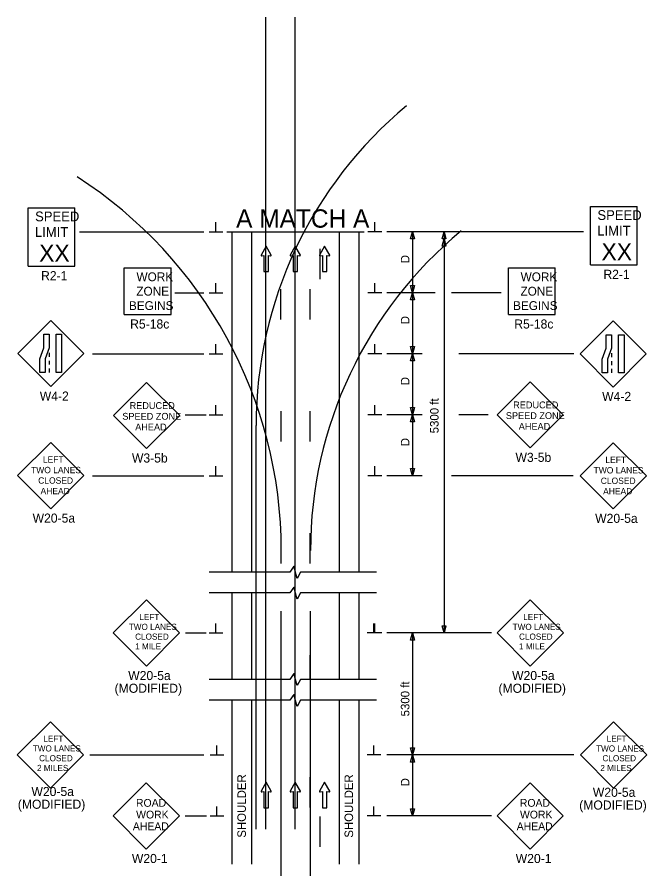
# Model space of a CAD drawing. Extents: x 16728 to 19508, y 5553 to 7079.
# Drawn here: x 17851 to 18367, y 6375 to 7079 of the extents above; entities that cross this region are included whole.
import ezdxf

# ---------------------------------------------------------------- set-up
doc = ezdxf.new("R2010")
doc.units = 0
for name, color, linetype in [('ALI_LEGAL_EX', 7, 'Continuous'), ('MT_SCRATCH_LEVEL_E', 7, 'Continuous'), ('PAVT_EDGE_EX', 7, 'Continuous'), ('TRAFFIC_SIGNS_PR', 7, 'Continuous'), ('TYPICAL_TEXT_DIMEN_PR', 7, 'Continuous')]:
    doc.layers.add(name, color=color, linetype=linetype)

msp = doc.modelspace()

# ---------------------------------------------------------------- linework, layer by layer
at = {"layer": 'ALI_LEGAL_EX'}
for p, q in [((18054.48, 7078.99), (18054.48, 6413.36)), ((18078.48, 7078.99), (18078.48, 6413.36)), ((18054.48, 6981.91), (18054.48, 6413.36)), ((18078.48, 6981.91), (18078.48, 6413.36)), ((18046.81, 6413.36), (18046.81, 6744.25)), ((18067.05, 6592.15), (18067.05, 6515)), ((18067.45, 6375.08), (18067.45, 6591.74)), ((18091.05, 6592.15), (18091.05, 6515)), ((18091.45, 6375.08), (18091.45, 6591.74)), ((18067.05, 6569), (18067.05, 6375.08)), ((18091.05, 6569), (18091.05, 6375.08))]:
    msp.add_line(p, q, dxfattribs=at)
for points in [[(18099.19, 6889.18), (18099.19, 6864.18)], [(18067.05, 6831.03), (18067.05, 6856.03)], [(18091.05, 6831.03), (18091.05, 6856.03)], [(18067.05, 6756.03), (18067.05, 6731.03)], [(18067.05, 6756.03), (18067.05, 6731.03)], [(18091.05, 6731.03), (18091.05, 6756.03)], [(18067.05, 6656.03), (18067.05, 6631.03)], [(18067.05, 6656.03), (18067.05, 6631.03)], [(18091.05, 6631.03), (18091.05, 6656.03)], [(18067.05, 6556.03), (18067.05, 6531.03)], [(18067.05, 6556.03), (18067.05, 6536.14)], [(18091.05, 6536.14), (18091.05, 6556.03)], [(18067.05, 6456.03), (18067.05, 6431.03)], [(18067.05, 6456.03), (18067.05, 6431.03)], [(18091.05, 6431.03), (18091.05, 6456.03)], [(18099.19, 6423.79), (18099.19, 6398.79)]]:
    msp.add_lwpolyline(points, dxfattribs=at)
for centre, radius, start, end in [((18386.81, 6744.25), 340, 129.56655, 180), ((17703.45, 6641.72), 364, 0, 57.29578), ((18431.45, 6641.72), 340, 129.56655, 180)]:
    msp.add_arc(centre, radius, start, end, dxfattribs=at)
at = {"layer": 'MT_SCRATCH_LEVEL_E'}
for p, q in [((18055.05, 6891.26), (18050.94, 6884.02)), ((18059.19, 6884.02), (18055.05, 6891.26)), ((18078.95, 6891.26), (18074.84, 6884.02)), ((18083.1, 6884.02), (18078.95, 6891.26)), ((18103, 6891.26), (18098.89, 6884.02)), ((18107.15, 6884.02), (18103, 6891.26)), ((18051.42, 6883.34), (18053.19, 6883.65)), ((18053.19, 6883.65), (18053.19, 6870.4)), ((18056.94, 6870.4), (18056.94, 6883.65)), ((18056.94, 6883.65), (18058.71, 6883.34)), ((18075.32, 6883.34), (18077.1, 6883.65)), ((18077.1, 6883.65), (18077.1, 6870.4)), ((18080.84, 6870.4), (18080.84, 6883.65)), ((18080.84, 6883.65), (18082.62, 6883.34)), ((18099.37, 6883.34), (18101.15, 6883.65)), ((18101.15, 6883.65), (18101.15, 6870.4)), ((18104.89, 6870.4), (18104.89, 6883.65)), ((18104.89, 6883.65), (18106.67, 6883.34)), ((18053.19, 6870.4), (18056.94, 6870.4)), ((18077.1, 6870.4), (18080.84, 6870.4)), ((18101.15, 6870.4), (18104.89, 6870.4)), ((18055.05, 6451.78), (18050.94, 6444.54)), ((18059.19, 6444.54), (18055.05, 6451.78)), ((18078.95, 6451.78), (18074.84, 6444.54)), ((18083.1, 6444.54), (18078.95, 6451.78)), ((18103, 6451.78), (18098.89, 6444.54)), ((18107.15, 6444.54), (18103, 6451.78)), ((18051.42, 6443.86), (18053.19, 6444.17)), ((18053.19, 6444.17), (18053.19, 6430.92)), ((18056.94, 6430.92), (18056.94, 6444.17)), ((18056.94, 6444.17), (18058.71, 6443.86)), ((18075.32, 6443.86), (18077.1, 6444.17)), ((18077.1, 6444.17), (18077.1, 6430.92)), ((18080.84, 6430.92), (18080.84, 6444.17)), ((18080.84, 6444.17), (18082.62, 6443.86)), ((18099.37, 6443.86), (18101.15, 6444.17)), ((18101.15, 6444.17), (18101.15, 6430.92)), ((18104.89, 6430.92), (18104.89, 6444.17)), ((18104.89, 6444.17), (18106.67, 6443.86)), ((18053.19, 6430.92), (18056.94, 6430.92)), ((18077.1, 6430.92), (18080.84, 6430.92)), ((18101.15, 6430.92), (18104.89, 6430.92))]:
    msp.add_line(p, q, dxfattribs=at)
for centre, start, end in [((18051.34, 6883.8), 150.42484, 279.96381), ((18058.78, 6883.8), 260.03619, 29.77312), ((18075.25, 6883.8), 150.42484, 279.96381), ((18082.69, 6883.8), 260.03619, 29.77312), ((18099.3, 6883.8), 150.42484, 279.96381), ((18106.74, 6883.8), 260.03619, 29.77312), ((18051.34, 6444.32), 150.42484, 279.96381), ((18058.78, 6444.32), 260.03619, 29.77312), ((18075.25, 6444.32), 150.42484, 279.96381), ((18082.69, 6444.32), 260.03619, 29.77312), ((18099.3, 6444.32), 150.42484, 279.96381), ((18106.74, 6444.32), 260.03619, 29.77312)]:
    msp.add_arc(centre, 0.463, start, end, dxfattribs=at)
at = {"layer": 'PAVT_EDGE_EX'}
for p, q in [((18027.05, 6903.04), (18027.05, 6624.09)), ((18043.05, 6903.04), (18043.05, 6624.09)), ((18115.05, 6903.04), (18115.05, 6624.09)), ((18131.05, 6903.04), (18131.05, 6624.09)), ((18027.05, 6606.96), (18027.05, 6536.14)), ((18043.05, 6606.96), (18043.05, 6536.14)), ((18115.05, 6606.96), (18115.05, 6536.14)), ((18131.05, 6606.96), (18131.05, 6536.14)), ((18027.05, 6519), (18027.05, 6384.62)), ((18043.05, 6519), (18043.05, 6384.62)), ((18115.05, 6519), (18115.05, 6384.62)), ((18131.05, 6519), (18131.05, 6384.62))]:
    msp.add_line(p, q, dxfattribs=at)
at = {"layer": 'TRAFFIC_SIGNS_PR'}
for p, q in [((17859.91, 6922.8), (17898.31, 6922.8)), ((17859.91, 6874.8), (17859.91, 6922.8)), ((17898.31, 6874.8), (17898.31, 6922.8)), ((18320.85, 6923.9), (18359.25, 6923.9)), ((18320.85, 6875.9), (18320.85, 6923.9)), ((18359.25, 6875.9), (18359.25, 6923.9)), ((17859.91, 6874.8), (17898.31, 6874.8)), ((17938.79, 6835.18), (17938.79, 6873.58)), ((17938.79, 6873.58), (17977.19, 6873.58)), ((17977.19, 6835.18), (17977.19, 6873.58)), ((18253.66, 6835.18), (18253.66, 6873.58)), ((18253.66, 6873.58), (18292.06, 6873.58)), ((18292.06, 6835.18), (18292.06, 6873.58)), ((18320.85, 6875.9), (18359.25, 6875.9)), ((17938.79, 6835.18), (17977.19, 6835.18)), ((18253.66, 6835.18), (18292.06, 6835.18)), ((17878.55, 6830.41), (17851.4, 6803.26)), ((17905.71, 6803.26), (17878.55, 6830.41)), ((18339.51, 6830.11), (18312.36, 6802.96)), ((18366.67, 6802.96), (18339.51, 6830.11)), ((17851.4, 6803.26), (17878.55, 6776.11)), ((17877.31, 6803.75), (17877.31, 6800.55)), ((17878.55, 6776.11), (17905.71, 6803.26)), ((18312.36, 6802.96), (18339.51, 6775.81)), ((18338.27, 6803.45), (18338.27, 6800.25)), ((18339.51, 6775.81), (18366.67, 6802.96)), ((17877.31, 6797.35), (17877.31, 6794.15)), ((18338.27, 6797.05), (18338.27, 6793.85)), ((17877.31, 6790.95), (17877.31, 6787.75)), ((18338.27, 6790.65), (18338.27, 6787.45)), ((17957.12, 6779.63), (17929.96, 6752.48)), ((17984.27, 6752.48), (17957.12, 6779.63)), ((18271.51, 6780.17), (18244.36, 6753.02)), ((18298.66, 6753.02), (18271.51, 6780.17)), ((17929.96, 6752.48), (17957.12, 6725.33)), ((17957.12, 6725.33), (17984.27, 6752.48)), ((18244.36, 6753.02), (18271.51, 6725.87)), ((18271.51, 6725.87), (18298.66, 6753.02)), ((17878.5, 6730.36), (17851.35, 6703.21)), ((17905.66, 6703.21), (17878.5, 6730.36)), ((18339.61, 6730.16), (18312.46, 6703)), ((18366.76, 6703), (18339.61, 6730.16)), ((17851.35, 6703.21), (17878.5, 6676.06)), ((17878.5, 6676.06), (17905.66, 6703.21)), ((18312.46, 6703), (18339.61, 6675.85)), ((18339.61, 6675.85), (18366.76, 6703)), ((17956.88, 6601.39), (17929.69, 6574.2)), ((17984.06, 6574.2), (17956.88, 6601.39)), ((18271.53, 6601.39), (18244.35, 6574.2)), ((18298.72, 6574.2), (18271.53, 6601.39)), ((17929.69, 6574.2), (17956.88, 6547.01)), ((17956.88, 6547.01), (17984.06, 6574.2)), ((18244.35, 6574.2), (18271.53, 6547.02)), ((18271.53, 6547.02), (18298.72, 6574.2)), ((17878.18, 6501.43), (17850.99, 6474.24)), ((17905.36, 6474.24), (17878.18, 6501.43)), ((18339.92, 6501.39), (18312.73, 6474.2)), ((18367.11, 6474.2), (18339.92, 6501.39)), ((17850.99, 6474.24), (17878.18, 6447.06)), ((17878.18, 6447.06), (17905.36, 6474.24)), ((18312.73, 6474.2), (18339.92, 6447.01)), ((18339.92, 6447.01), (18367.11, 6474.2)), ((17956.85, 6451.32), (17929.69, 6424.16)), ((17984, 6424.16), (17956.85, 6451.32)), ((18271.49, 6451.32), (18244.34, 6424.16)), ((18298.64, 6424.16), (18271.49, 6451.32)), ((17929.69, 6424.16), (17956.85, 6397.01)), ((17956.85, 6397.01), (17984, 6424.16)), ((18244.34, 6424.16), (18271.49, 6397.01)), ((18271.49, 6397.01), (18298.64, 6424.16))]:
    msp.add_line(p, q, dxfattribs=at)
for points in [[(17877.31, 6819), (17877.31, 6807.82), (17873.96, 6798.93), (17873.96, 6787.75), (17869.47, 6787.75), (17869.47, 6798.93), (17872.81, 6807.82), (17872.81, 6819)], [(17887.44, 6819), (17887.44, 6787.75), (17882.95, 6787.75), (17882.95, 6819)], [(18338.27, 6818.7), (18338.27, 6807.52), (18334.92, 6798.63), (18334.92, 6787.45), (18330.43, 6787.45), (18330.43, 6798.63), (18333.77, 6807.52), (18333.77, 6818.7)], [(18348.4, 6818.7), (18348.4, 6787.45), (18343.91, 6787.45), (18343.91, 6818.7)]]:
    msp.add_lwpolyline(points, close=True, dxfattribs=at)
at = {"layer": 'TYPICAL_TEXT_DIMEN_PR'}
for p, q in [((18013.92, 6903.04), (18013.92, 6910.83)), ((18144.17, 6903.04), (18144.17, 6910.83)), ((17902.17, 6903.04), (18004.05, 6903.04)), ((18008.3, 6903.04), (18019.55, 6903.04)), ((18022.72, 6903.04), (18135.37, 6903.04)), ((18149.8, 6903.04), (18138.55, 6903.04)), ((18315.22, 6903.04), (18154.05, 6903.04)), ((18173.48, 6897.18), (18175.05, 6903.04)), ((18175.05, 6903.04), (18175.05, 6853.04)), ((18175.05, 6903.04), (18176.62, 6897.18)), ((18199.32, 6897.18), (18200.89, 6903.04)), ((18200.89, 6903.04), (18200.89, 6574.2)), ((18200.89, 6903.04), (18202.46, 6897.18)), ((18175.05, 6897.18), (18173.48, 6897.18)), ((18176.62, 6897.18), (18175.05, 6897.18)), ((18199.32, 6891.4), (18200.89, 6897.27)), ((18200.89, 6897.18), (18199.32, 6897.18)), ((18200.89, 6891.4), (18199.32, 6891.4)), ((18200.89, 6897.27), (18202.46, 6891.4)), ((18202.46, 6897.18), (18200.89, 6897.18)), ((18202.46, 6891.4), (18200.89, 6891.4)), ((18013.92, 6853.04), (18013.92, 6860.83)), ((18144.17, 6853.04), (18144.17, 6860.83)), ((18175.05, 6853.04), (18173.48, 6858.91)), ((18173.48, 6858.91), (18175.05, 6858.91)), ((18175.05, 6858.91), (18176.62, 6858.91)), ((18176.62, 6858.91), (18175.05, 6853.04)), ((17980.24, 6853.04), (18004.05, 6853.04)), ((18008.3, 6853.04), (18019.55, 6853.04)), ((18149.8, 6853.04), (18138.55, 6853.04)), ((18193.6, 6853.04), (18154.05, 6853.04)), ((18173.48, 6847.18), (18175.05, 6853.04)), ((18175.05, 6853.04), (18175.05, 6803.04)), ((18175.05, 6853.04), (18176.62, 6847.18)), ((18247.8, 6853.04), (18206.89, 6853.04)), ((18175.05, 6847.18), (18173.48, 6847.18)), ((18176.62, 6847.18), (18175.05, 6847.18)), ((18013.92, 6803.04), (18013.92, 6810.83)), ((18144.17, 6803.04), (18144.17, 6810.83)), ((18175.05, 6803.04), (18173.48, 6808.91)), ((18173.48, 6808.91), (18175.05, 6808.91)), ((18175.05, 6808.91), (18176.62, 6808.91)), ((18176.62, 6808.91), (18175.05, 6803.04)), ((17912.81, 6803.04), (18004.05, 6803.04)), ((18008.3, 6803.04), (18019.55, 6803.04)), ((18149.8, 6803.04), (18138.55, 6803.04)), ((18183.05, 6803.04), (18154.05, 6803.04)), ((18173.48, 6797.18), (18175.05, 6803.04)), ((18175.05, 6803.04), (18175.05, 6753.04)), ((18175.05, 6803.04), (18176.62, 6797.18)), ((18307.28, 6803.04), (18212.91, 6803.04)), ((18175.05, 6797.18), (18173.48, 6797.18)), ((18176.62, 6797.18), (18175.05, 6797.18)), ((18013.92, 6753.04), (18013.92, 6760.83)), ((18144.17, 6753.04), (18144.17, 6760.83)), ((18175.05, 6753.04), (18173.48, 6758.91)), ((18173.48, 6758.91), (18175.05, 6758.91)), ((18175.05, 6758.91), (18176.62, 6758.91)), ((18176.62, 6758.91), (18175.05, 6753.04)), ((17988.64, 6753.04), (18005.82, 6753.04)), ((18008.3, 6753.04), (18019.55, 6753.04)), ((18149.8, 6753.04), (18138.55, 6753.04)), ((18183.05, 6753.04), (18154.05, 6753.04)), ((18173.48, 6747.18), (18175.05, 6753.04)), ((18175.05, 6753.04), (18175.05, 6703.04)), ((18175.05, 6753.04), (18176.62, 6747.18)), ((18237.15, 6753.04), (18212.91, 6753.04)), ((18175.05, 6747.18), (18173.48, 6747.18)), ((18176.62, 6747.18), (18175.05, 6747.18)), ((18013.92, 6703.04), (18013.92, 6710.83)), ((18144.17, 6703.04), (18144.17, 6710.83)), ((18175.05, 6703.04), (18173.48, 6708.91)), ((18173.48, 6708.91), (18175.05, 6708.91)), ((18175.05, 6708.91), (18176.62, 6708.91)), ((18176.62, 6708.91), (18175.05, 6703.04)), ((17912.81, 6703.04), (18004.05, 6703.04)), ((18008.3, 6703.04), (18019.55, 6703.04)), ((18149.8, 6703.04), (18138.55, 6703.04)), ((18183.05, 6703.04), (18154.05, 6703.04)), ((18306.74, 6703.04), (18206.97, 6703.04)), ((18074.4, 6624.09), (18008.45, 6624.09)), ((18077.65, 6628.89), (18074.4, 6624.09)), ((18080.39, 6618.95), (18077.65, 6628.89)), ((18083.14, 6624.09), (18080.39, 6618.95)), ((18145.47, 6624.09), (18083.14, 6624.09)), ((18077.65, 6611.76), (18074.4, 6606.96)), ((18080.39, 6601.82), (18077.65, 6611.76)), ((18074.4, 6606.96), (18008.45, 6606.96)), ((18083.14, 6606.96), (18080.39, 6601.82)), ((18145.47, 6606.96), (18083.14, 6606.96)), ((18013.92, 6574.2), (18013.92, 6581.98)), ((18143.42, 6574.2), (18143.42, 6581.98)), ((18144.17, 6574.2), (18144.17, 6581.98)), ((18200.89, 6574.2), (18199.32, 6580.06)), ((18199.32, 6580.06), (18200.89, 6580.06)), ((18200.89, 6580.06), (18202.46, 6580.06)), ((18202.46, 6580.06), (18200.89, 6574.2)), ((17989.09, 6574.2), (18005.82, 6574.2)), ((18008.3, 6574.2), (18019.55, 6574.2)), ((18149.05, 6574.2), (18137.8, 6574.2)), ((18149.8, 6574.2), (18138.55, 6574.2)), ((18239.66, 6574.2), (18154.05, 6574.2)), ((18173.48, 6568.34), (18175.05, 6574.2)), ((18175.05, 6568.34), (18173.48, 6568.34)), ((18175.05, 6574.2), (18175.05, 6474.2)), ((18175.05, 6574.2), (18176.62, 6568.34)), ((18176.62, 6568.34), (18175.05, 6568.34)), ((18077.65, 6540.94), (18074.4, 6536.14)), ((18080.39, 6531), (18077.65, 6540.94)), ((18074.4, 6536.14), (18008.45, 6536.14)), ((18083.14, 6536.14), (18080.39, 6531)), ((18145.47, 6536.14), (18083.14, 6536.14)), ((18074.4, 6519), (18008.45, 6519)), ((18077.65, 6523.8), (18074.4, 6519)), ((18080.39, 6513.86), (18077.65, 6523.8)), ((18083.14, 6519), (18080.39, 6513.86)), ((18145.47, 6519), (18083.14, 6519)), ((18014.67, 6474.2), (18014.67, 6481.98)), ((18143.42, 6474.2), (18143.42, 6481.98)), ((18175.05, 6474.2), (18173.48, 6480.06)), ((18173.48, 6480.06), (18175.05, 6480.06)), ((18175.05, 6480.06), (18176.62, 6480.06)), ((18176.62, 6480.06), (18175.05, 6474.2)), ((17910.62, 6474.2), (18004.05, 6474.2)), ((18009.05, 6474.2), (18020.3, 6474.2)), ((18149.05, 6474.2), (18137.8, 6474.2)), ((18307.28, 6474.2), (18154.05, 6474.2)), ((18173.48, 6468.34), (18175.05, 6474.2)), ((18175.05, 6474.2), (18175.05, 6424.2)), ((18175.05, 6474.2), (18176.62, 6468.34)), ((18175.05, 6468.34), (18173.48, 6468.34)), ((18176.62, 6468.34), (18175.05, 6468.34)), ((18014.67, 6424.2), (18014.67, 6431.98)), ((18143.42, 6424.2), (18143.42, 6431.98)), ((18175.05, 6424.2), (18173.48, 6430.06)), ((18173.48, 6430.06), (18175.05, 6430.06)), ((18175.05, 6430.06), (18176.62, 6430.06)), ((18176.62, 6430.06), (18175.05, 6424.2)), ((17988.76, 6424.2), (18006.27, 6424.2)), ((18009.05, 6424.2), (18020.3, 6424.2)), ((18149.05, 6424.2), (18137.8, 6424.2)), ((18239.88, 6424.2), (18154.05, 6424.2))]:
    msp.add_line(p, q, dxfattribs=at)

# ---------------------------------------------------------------- texts
at = {"layer": 'TRAFFIC_SIGNS_PR'}
for s, height, p in [('SPEED', 8, (17865.68, 6911.66)), ('SPEED', 8, (18326.62, 6912.77)), ('LIMIT', 8, (17865.51, 6898.86)), ('LIMIT', 8, (18326.46, 6899.97)), ('XX', 14.031, (17869.02, 6878.56)), ('XX', 14.031, (18329.96, 6879.66)), ('R2-1', 7.44, (17870.58, 6863.36)), ('R2-1', 7.44, (18331.53, 6864.47)), ('WORK', 7.217, (17948.79, 6862.54)), ('WORK', 7.217, (18263.66, 6862.54)), ('ZONE', 7.217, (17948.67, 6850.73)), ('ZONE', 7.217, (18263.54, 6850.73)), ('BEGINS', 7.217, (17942.6, 6838.93)), ('BEGINS', 7.217, (18257.47, 6838.93)), ('R5-18c', 7.44, (17943.6, 6823.74)), ('R5-18c', 7.44, (18258.47, 6823.74)), ('W4-2', 7.44, (17869.51, 6764.67)), ('W4-2', 7.44, (18330.47, 6764.37)), ('REDUCED', 5.6, (17943.17, 6757.79)), ('REDUCED', 5.6, (18257.57, 6758.33)), ('SPEED ZONE', 5.6, (17937.17, 6748.99)), ('SPEED ZONE', 5.6, (18251.56, 6749.53)), ('AHEAD', 5.6, (17947.73, 6740.19)), ('AHEAD', 5.6, (18262.12, 6740.73)), ('LEFT', 5.2, (17872.04, 6713.75)), ('W3-5b', 7.44, (17945.07, 6713.89)), ('W3-5b', 7.44, (18259.46, 6714.43)), ('LEFT', 5.2, (18333.15, 6713.55)), ('TWO LANES', 5.2, (17862.37, 6705.15)), ('TWO LANES', 5.2, (18323.47, 6704.95)), ('CLOSED', 5.2, (17868.22, 6696.55)), ('CLOSED', 5.2, (18329.33, 6696.35)), ('AHEAD', 5.2, (17870.16, 6687.95)), ('AHEAD', 5.2, (18331.27, 6687.75)), ('W20-5a', 7.44, (17863.64, 6664.62)), ('W20-5a', 7.44, (18324.75, 6664.42)), ('LEFT', 5.006, (17951.12, 6584.69)), ('LEFT', 5.006, (18265.78, 6584.69)), ('TWO LANES', 5.006, (17942.47, 6576.69)), ('TWO LANES', 5.006, (18257.12, 6576.69)), ('CLOSED', 5.006, (17947.7, 6568.68)), ('CLOSED', 5.006, (18262.36, 6568.68)), ('1 MILE', 5.006, (17947.69, 6560.67)), ('1 MILE', 5.006, (18262.35, 6560.67)), ('W20-5a', 7.449, (17942, 6535.56)), ('W20-5a', 7.449, (18256.66, 6535.56)), ('(MODIFIED)', 7.449, (17930.84, 6525.11)), ('(MODIFIED)', 7.449, (18245.5, 6525.11)), ('LEFT', 5.006, (17872.42, 6485.04)), ('LEFT', 5.006, (18334.16, 6484.99)), ('TWO LANES', 5.006, (17863.77, 6477.03)), ('TWO LANES', 5.006, (18325.51, 6476.99)), ('CLOSED', 5.006, (17869, 6469.02)), ('CLOSED', 5.006, (18330.75, 6468.98)), ('2 MILES', 5.006, (17867.25, 6461.02)), ('2 MILES', 5.006, (18328.99, 6460.97)), ('W20-5a', 7.449, (17862.67, 6440.49)), ('W20-5a', 7.449, (18322.86, 6439.84)), ('(MODIFIED)', 7.449, (17851.51, 6430.04)), ('ROAD', 6.4, (17948.39, 6431.7)), ('ROAD', 6.4, (18263.03, 6431.7)), ('(MODIFIED)', 7.449, (18311.7, 6429.39)), ('WORK', 6.4, (17948.5, 6422.1)), ('WORK', 6.4, (18263.14, 6422.1)), ('AHEAD', 6.4, (17945.81, 6412.5)), ('AHEAD', 6.4, (18260.45, 6412.5)), ('W20-1', 7.44, (17945.02, 6385.57)), ('W20-1', 7.44, (18259.66, 6385.57))]:
    msp.add_text(s, height=height, dxfattribs=at).set_placement(p)
at = {"layer": 'TYPICAL_TEXT_DIMEN_PR'}
msp.add_text('A MATCH A', height=15, dxfattribs=at).set_placement((18030.46, 6906.45))
for s, p in [('D', (18172.49, 6877.26)), ('D', (18172.49, 6827.26)), ('D', (18172.49, 6777.26)), ('5300 ft', (18196.43, 6737.84)), ('D', (18172.49, 6727.26)), ('5300 ft', (18172.49, 6505.81)), ('SHOULDER', (18038.47, 6406.33)), ('SHOULDER', (18126.33, 6406.33)), ('D', (18172.49, 6448.42))]:
    msp.add_text(s, height=7, rotation=90, dxfattribs=at).set_placement(p)

doc.saveas('drawing.dxf')
